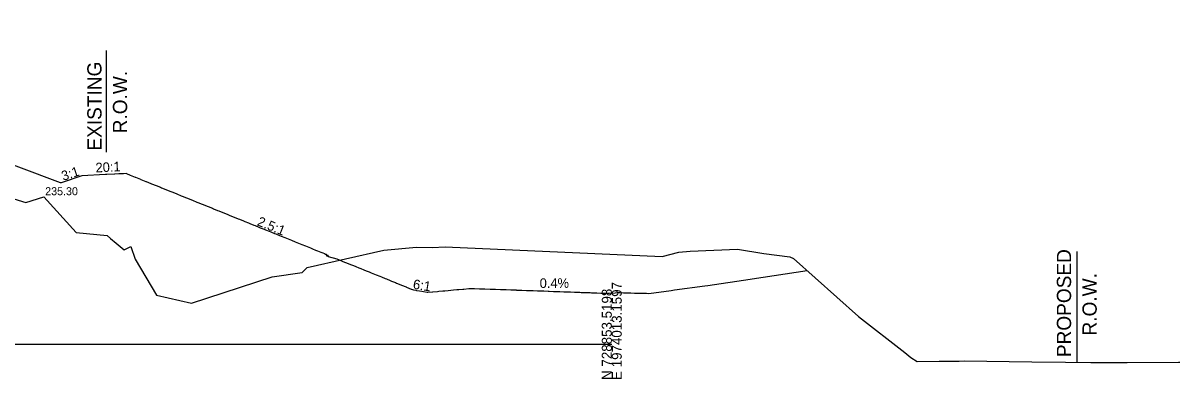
# Model space of a CAD drawing. Extents: x -26 to 630, y -39 to 9098.
# Drawn here: x 284.5 to 609.7, y 2990.3 to 3090.2 of the extents above; entities that cross this region are included whole.
import ezdxf

# ---------------------------------------------------------------- set-up
doc = ezdxf.new("R2010")
doc.units = 0
for name, color, linetype in [('CONST_DCH', 7, 'Continuous'), ('Default', 7, 'Continuous'), ('DTM CONTOURS_MAJOR', 7, 'Continuous'), ('DTM_X_GROUND', 7, 'Continuous'), ('X_DTM_CONTOURS_MAJOR', 7, 'Continuous'), ('XS_CELL', 7, 'Continuous'), ('XS_P_GROUND', 7, 'Continuous'), ('XS_P_ROW', 7, 'Continuous'), ('XS_P_TX_DCH', 7, 'Continuous'), ('XS_P_TX_FS_BS', 7, 'Continuous'), ('XS_X_ROW', 7, 'Continuous')]:
    doc.layers.add(name, color=color, linetype=linetype)

msp = doc.modelspace()

# ---------------------------------------------------------------- linework, layer by layer
at = {"layer": 'DTM_X_GROUND'}
msp.add_lwpolyline([(281.91, 3040.81), (285.31, 3039.78), (290.3, 3041.43), (299.43, 3031.42), (308.13, 3030.57), (309.07, 3029.73), (310.67, 3028.39), (312.93, 3026.52), (314.28, 3027.18), (314.82, 3027.45), (316.02, 3023.91), (322.04, 3013.84), (331.89, 3011.51), (354.49, 3018.98), (363, 3020.13), (364.41, 3021.58), (385.96, 3026.4), (395.07, 3027.23), (399.5, 3027.18), (403.2, 3027.32), (464.2, 3024.62), (468.85, 3025.9), (472.08, 3026.17), (485.36, 3026.72), (492.72, 3025.5), (500.04, 3024.57), (501.09, 3024.11), (519.37, 3007.85), (532.41, 2997.71), (534.08, 2996.27), (535.88, 2995.15), (542.05, 2995.23), (547.62, 2995.31), (549.07, 2995.32), (568.1, 2995.11), (577.57, 2995.01), (584.63, 2994.92), (594.93, 2994.89), (609.34, 2994.98), (609.7, 2994.95)], dxfattribs=at)
at = {"layer": 'XS_CELL'}
msp.add_line((100, 3000), (450, 3000), dxfattribs=at)
at = {"layer": 'XS_P_GROUND'}
for points in [[(313.59, 3047.92), (312.72, 3047.88), (312.65, 3047.88), (311.48, 3047.82), (311.44, 3047.82), (310.29, 3047.76), (310.23, 3047.76), (308.01, 3047.64), (307.69, 3047.63), (301.07, 3047.3), (295.22, 3045.35), (295.07, 3045.3), (258.32, 3059.11), (257.29, 3059.5), (251.73, 3061.59), (251.58, 3061.65), (220.72, 3073.25), (220, 3073.52), (206.35, 3072.84), (206, 3072.82), (200.15, 3070.87), (200, 3070.82), (198.57, 3071.3), (142, 3090.15)], [(313.59, 3047.92), (314.6, 3047.52), (314.63, 3047.51), (316.06, 3046.93), (316.13, 3046.9), (317.53, 3046.34), (317.64, 3046.29), (318.99, 3045.74), (319.14, 3045.68), (320.45, 3045.15), (320.64, 3045.08), (321.92, 3044.56), (323.14, 3044.07), (323.38, 3043.97), (324.6, 3043.48), (324.85, 3043.38), (326.06, 3042.89), (326.31, 3042.79), (327.52, 3042.3), (327.77, 3042.2), (328.98, 3041.71), (329.24, 3041.61), (330.44, 3041.12), (330.7, 3041.02), (331.89, 3040.53), (332.17, 3040.42), (333.35, 3039.95), (333.63, 3039.83), (334.81, 3039.36), (335.09, 3039.24), (336.26, 3038.77), (336.56, 3038.65), (337.72, 3038.18), (338.02, 3038.06), (339.18, 3037.59), (339.49, 3037.47), (340.63, 3037.01), (340.95, 3036.88), (342.09, 3036.42), (342.41, 3036.29), (343.54, 3035.83), (343.88, 3035.69), (345, 3035.24), (345.34, 3035.1), (346.45, 3034.66), (346.81, 3034.51), (347.91, 3034.07), (348.27, 3033.92), (349.36, 3033.48), (349.74, 3033.33), (350.81, 3032.9), (351.2, 3032.74), (352.26, 3032.31), (352.66, 3032.15), (353.72, 3031.72), (354.13, 3031.56), (355.17, 3031.14), (355.59, 3030.97), (356.62, 3030.55), (357.06, 3030.37), (358.07, 3029.97), (358.52, 3029.78), (359.52, 3029.38), (359.98, 3029.19), (360.97, 3028.8), (361.45, 3028.6), (362.41, 3028.21), (362.91, 3028.01), (363.86, 3027.63), (364.38, 3027.42), (365.31, 3027.04), (365.84, 3026.83), (366.75, 3026.46), (367.3, 3026.24), (368.2, 3025.88), (368.77, 3025.65), (369.21, 3025.47), (369.51, 3025.35), (369.81, 3025.22), (369.57, 3025.21), (370.31, 3024.91), (369.71, 3024.94), (370.35, 3024.68), (370.3, 3024.64), (372.69, 3023.99), (372.93, 3023.89), (373.69, 3023.58), (374.41, 3023.29), (375.14, 3023), (375.89, 3022.69), (376.59, 3022.41), (377.37, 3022.09), (378.03, 3021.83), (378.85, 3021.5), (379.48, 3021.24), (380.33, 3020.9), (380.92, 3020.66), (381.81, 3020.3), (382.35, 3020.08), (383.29, 3019.7), (383.79, 3019.5), (384.77, 3019.1), (385.22, 3018.92), (386.25, 3018.51), (386.65, 3018.34), (387.73, 3017.91), (388.07, 3017.77), (389.2, 3017.31), (389.48, 3017.2), (390.68, 3016.71), (390.89, 3016.63), (392.16, 3016.11), (392.29, 3016.06), (393.64, 3015.51), (393.68, 3015.5), (394.22, 3015.28), (394.88, 3015.18), (395.12, 3015.14), (395.97, 3015), (396.6, 3014.9), (397.05, 3014.83), (398.08, 3014.67), (398.14, 3014.66), (398.29, 3014.63)], [(398.29, 3014.63), (399.56, 3014.74), (399.74, 3014.76), (401.04, 3014.87), (401.42, 3014.91), (402.52, 3015), (403.1, 3015.05), (404, 3015.13), (404.79, 3015.2), (405.48, 3015.26), (406.47, 3015.35), (406.96, 3015.39), (408.15, 3015.49), (408.44, 3015.52), (409.84, 3015.64), (409.92, 3015.65), (410.5, 3015.7), (411.38, 3015.67), (411.4, 3015.67), (412.84, 3015.61), (412.88, 3015.61), (414.31, 3015.56), (414.35, 3015.56), (415.77, 3015.51), (415.83, 3015.51), (417.23, 3015.46), (417.31, 3015.45), (418.69, 3015.4), (418.79, 3015.4), (420.16, 3015.35), (420.27, 3015.35), (421.62, 3015.3), (421.75, 3015.29), (423.09, 3015.25), (423.23, 3015.24), (424.55, 3015.19), (424.71, 3015.19), (426.01, 3015.14), (426.19, 3015.14), (426.37, 3015.13), (427.67, 3015.08), (427.87, 3015.07), (429.15, 3015.03), (429.37, 3015.02), (430.63, 3014.98), (430.86, 3014.97), (432.11, 3014.92), (432.36, 3014.91), (433.59, 3014.87), (433.86, 3014.86), (435.07, 3014.82), (435.36, 3014.81), (436.55, 3014.76), (436.85, 3014.75), (438.03, 3014.71), (438.35, 3014.7), (439.5, 3014.66), (439.85, 3014.65), (440.98, 3014.61), (441.35, 3014.59), (442.46, 3014.55), (442.84, 3014.54), (443.94, 3014.5), (444.34, 3014.48), (445.42, 3014.45), (445.84, 3014.43), (446.9, 3014.39), (447.34, 3014.38), (448.38, 3014.34), (448.65, 3014.33), (449.27, 3014.31), (450.98, 3014.49), (451.76, 3014.53), (452.29, 3014.51), (453.29, 3014.48), (453.84, 3014.47), (454.82, 3014.44), (455.39, 3014.43), (456.35, 3014.4), (456.94, 3014.39), (457.88, 3014.36), (458.49, 3014.34), (459.42, 3014.32), (459.8, 3014.31), (460.37, 3014.29), (466.74, 3015.13), (467.66, 3015.25), (476.15, 3016.43), (476.97, 3016.55), (488.94, 3018.3), (489.49, 3018.38), (504.9, 3020.75)]]:
    msp.add_lwpolyline(points, dxfattribs=at)
at = {"layer": 'XS_P_ROW'}
msp.add_line((580.73, 3026.04), (580.73, 2995.02), dxfattribs=at)
at = {"layer": 'XS_X_ROW'}
msp.add_line((308, 3053.97), (308, 3082.48), dxfattribs=at)

# ---------------------------------------------------------------- texts
at = {"layer": 'CONST_DCH'}
msp.add_text('X', height=0.001, dxfattribs=at).set_placement((410.5, 3015.7))
at = {"layer": 'Default'}
for p in [(295.03, 3045.24), (295.03, 3045.24), (375.08, 3023.92)]:
    msp.add_text('X', height=0.12, dxfattribs=at).set_placement(p)
at = {"layer": 'DTM CONTOURS_MAJOR'}
msp.add_text('X', height=0.001, dxfattribs=at).set_placement((295.07, 3045.3))
at = {"layer": 'X_DTM_CONTOURS_MAJOR'}
for height, p in [(0.12, (298.05, 3048.5)), (0.12, (298.05, 3048.5)), (0.12, (301.03, 3047.24)), (0.12, (301.03, 3047.24)), (0.001, (301.07, 3047.3)), (0.12, (315.03, 3047.94))]:
    msp.add_text('X', height=height, dxfattribs=at).set_placement(p)
at = {"layer": 'XS_CELL'}
for s, p in [('N 728853.5198', (450, 2990)), ('E 1974013.1597', (452.8, 2990))]:
    msp.add_text(s, height=2.8, rotation=90, dxfattribs=at).set_placement(p)
at = {"layer": 'XS_P_ROW'}
for s, p in [('EXISTING', (306.56, 3054.38)), ('R.O.W.', (313.76, 3059.23)), ('PROPOSED', (579.12, 2996.4)), ('R.O.W.', (586.32, 3002.47))]:
    msp.add_text(s, height=4, rotation=90, dxfattribs=at).set_placement(p)
at = {"layer": 'XS_P_TX_DCH'}
msp.add_text('235.30', height=2.25, dxfattribs=at).set_placement((290.72, 3041.85))
at = {"layer": 'XS_P_TX_FS_BS'}
for s, rotation, p in [('20:1', 2.8625, (304.95, 3048.24)), ('3:1', 18.4349, (295.8, 3045.86)), ('2.5:1', 337.959, (350.1, 3033.47)), ('6:1', 350.9849, (393.97, 3015.62)), ('0.4%', 0.2095, (429.74, 3015.82))]:
    msp.add_text(s, height=2.7, rotation=rotation, dxfattribs=at).set_placement(p)

doc.saveas('drawing.dxf')
